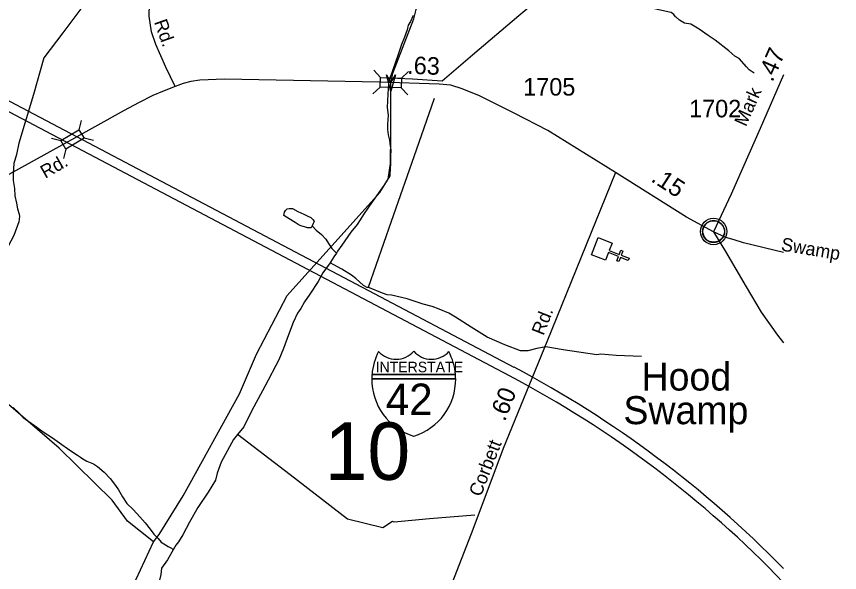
# Model space of a CAD drawing. Extents: x 2315291 to 2336543, y 597177 to 615230.
# Drawn here: x 2330575 to 2336451, y 602347 to 606314 of the extents above; entities that cross this region are included whole.
import ezdxf

# ---------------------------------------------------------------- set-up
doc = ezdxf.new("R2010")
doc.units = 0
for name, color, linetype in [('Exist Civil Demographics Community CELL', 7, 'Continuous'), ('Exist Civil Demographics Community Label', 7, 'Continuous'), ('Exist Cultural Church CELL', 7, 'Continuous'), ('Exist Hydrographic Creek Single Shore', 7, 'Continuous'), ('Exist Hydrographic Misc Water Feature', 7, 'Continuous'), ('Exist Road Primary US Attributed', 7, 'Continuous'), ('Exist Road Primary US Shield CELL', 7, 'Continuous'), ('Exist Road Primary US Shield Number Label', 7, 'Continuous'), ('Exist Road Secondary Mileage Hundredths English Label', 7, 'Continuous'), ('Exist Road Secondary Structure Standard Bridge Attributed CELL', 7, 'Continuous'), ('Exist Road Secondary Structure Standard Bridge CELL', 7, 'Continuous'), ('Exist Road Secondary Structure Standard Bridge Number Label', 7, 'Continuous'), ('Exist Road Secondary Type 51 Attributed', 7, 'Continuous'), ('Exist Road Secondary Type 51 Label', 7, 'Continuous'), ('Exist Road Secondary Type 51 Number Label', 7, 'Continuous')]:
    doc.layers.add(name, color=color, linetype=linetype)

msp = doc.modelspace()

# ---------------------------------------------------------------- linework, layer by layer
at = {"layer": 'Exist Civil Demographics Community CELL'}
msp.add_lwpolyline([(2335474.3, 604792.5), (2335475.3, 604798.1), (2335477.1, 604804.6), (2335480, 604811.8), (2335483, 604817.6), (2335486.3, 604823.3), (2335490.1, 604828.4), (2335494, 604832.8), (2335498.6, 604837.4), (2335504.1, 604842), (2335509.6, 604845.7), (2335514.4, 604848.5), (2335519.5, 604851), (2335525, 604853.3), (2335530.6, 604855.1), (2335534.9, 604856.2), (2335539.8, 604857), (2335543.9, 604857.7), (2335550.3, 604858), (2335554.7, 604857.9), (2335560.4, 604857.6), (2335565.3, 604856.9), (2335570.2, 604855.9), (2335575.2, 604854.5), (2335580.3, 604852.5), (2335587, 604849.6), (2335593.3, 604846.1), (2335598.3, 604842.6), (2335603.5, 604838.6), (2335606.8, 604835.4), (2335610.9, 604831), (2335614.8, 604826.3), (2335617.9, 604821.8), (2335621, 604816.7), (2335623.4, 604811.6), (2335625.5, 604806.6), (2335627, 604801.6), (2335628.3, 604797), (2335629.4, 604790.9), (2335630, 604786.2), (2335630.3, 604780.2), (2335630.1, 604774.4), (2335629.6, 604768.7), (2335628.6, 604763.3), (2335627, 604757.1), (2335625.1, 604751.3), (2335622.8, 604746.2), (2335619.6, 604740.2), (2335616.4, 604734.9), (2335612.9, 604730.2), (2335608.7, 604725.4), (2335603.4, 604720.5), (2335598.4, 604716.4), (2335593.4, 604712.9), (2335589, 604710.4), (2335582.2, 604707.2), (2335575.1, 604704.5), (2335569.1, 604703), (2335562.5, 604701.7), (2335558.1, 604701.2), (2335553.6, 604701), (2335548, 604701), (2335543.7, 604701.4), (2335538.1, 604702.1), (2335532.2, 604703.4), (2335527.6, 604704.7), (2335522.4, 604706.6), (2335517.8, 604708.6), (2335513.9, 604710.8), (2335507.1, 604714.9), (2335501.5, 604719.2), (2335496.6, 604723.7), (2335492.2, 604728.5), (2335489, 604732.5), (2335486, 604736.7), (2335481.9, 604743.8), (2335480.2, 604747.3), (2335478.5, 604751.3), (2335475.9, 604759.5), (2335474.3, 604766.6), (2335473.7, 604771.7), (2335473.3, 604778), (2335473.3, 604782.7), (2335473.8, 604789.2)], close=True, dxfattribs=at)
for centre, radius in [((2335552, 604780.1), 94.3), ((2335551.7, 604780.3), 76.7)]:
    msp.add_circle(centre, radius, dxfattribs=at)
at = {"layer": 'Exist Cultural Church CELL'}
msp.add_lwpolyline([(2334827.5, 604697.2), (2334806.8, 604644.1), (2334877.7, 604616.3), (2334889.4, 604646.1), (2334904.3, 604640.3), (2334892.6, 604610.5), (2334948.6, 604588.5), (2334942.7, 604573.6), (2334886.7, 604595.6), (2334875, 604565.8), (2334860.2, 604571.6), (2334871.8, 604601.4), (2334801, 604629.2), (2334779.8, 604575.6), (2334680.7, 604614.5), (2334728.4, 604736.1)], close=True, dxfattribs=at)
at = {"layer": 'Exist Hydrographic Creek Single Shore'}
for points in [[(2331553.5, 602566.1), (2331594.5, 602617), (2331766.4, 602893.1), (2332166.4, 603621.4), (2332288.4, 603905.2), (2332508.5, 604324.4), (2333168.2, 605058.9), (2333228.5, 605153.4), (2333244.6, 605266.1), (2333246.6, 605470.2), (2333248.1, 605841.5), (2333262.7, 605910.9), (2333411.5, 606298.5), (2333429.6, 606364.9), (2333467.8, 606503.8)], [(2331553.5, 602566.1), (2331368.4, 602712.9), (2331258.5, 602862.7), (2330879.5, 603234.6), (2330501.4, 603560.6)], [(2330983.5, 600534.7), (2330982.5, 600659.3), (2331029.4, 600936.9), (2331027.4, 601110.8), (2331050.5, 601243), (2331107.5, 601419.2), (2331430.5, 602298.7), (2331553.5, 602566.1)]]:
    msp.add_lwpolyline(points, dxfattribs=at)
at = {"layer": 'Exist Hydrographic Misc Water Feature'}
for points in [[(2331137.9, 606973.4), (2331096.5, 606687.2), (2331055.9, 606396.9), (2330906.2, 606197.6), (2330770, 606020.2), (2330696.6, 605757.5), (2330592.7, 605410.6), (2330575.4, 605328.4), (2330556.2, 605266), (2330553.1, 605195.9), (2330551.6, 605144.3), (2330560.3, 605086.2), (2330564.8, 605034.4), (2330575.4, 604982.5), (2330583.6, 604940.7), (2330595.9, 604904.8), (2330596.3, 604886.9), (2330592.7, 604848.9), (2330557.4, 604752.5), (2330493.2, 604629.9), (2330403.4, 604428.9), (2330321.2, 604254.3), (2330246.9, 604099.6)], [(2335284.9, 606308.6), (2335280.8, 606312.4), (2335268.5, 606328), (2335248.8, 606342), (2335224.2, 606347.7), (2334957.8, 606406.8), (2334551, 606496.4), (2334489.1, 606499.6), (2334418.9, 606509), (2334384.9, 606506.8), (2334161, 606318.2), (2333830.4, 606037.1), (2333614.3, 605852.6), (2333402.5, 605866.3), (2333240.7, 605874.8)], [(2333407.4, 606320.1), (2333388.1, 606278), (2333372.3, 606252), (2333364.8, 606219.9), (2333345.1, 606165.6), (2333323.5, 606115.4), (2333300.6, 606043.4), (2333281.3, 605989.1), (2333256.1, 605918.7), (2333242.5, 605880.6), (2333240.7, 605874.8)], [(2335842.4, 605909.6), (2335805.9, 605933.3), (2335785.8, 605955), (2335734.7, 606014.2), (2335703, 606031.9), (2335660.7, 606069.5), (2335563.5, 606144.2), (2335513.3, 606179.7), (2335448.7, 606222.7), (2335388, 606259), (2335343.7, 606266.1), (2335309.1, 606288.7), (2335284.9, 606308.6)], [(2333240.7, 605874.8), (2333230.4, 605836.6), (2333225.9, 605760.6), (2333222.7, 605664.6), (2333229.2, 605608.9), (2333224.1, 605542.7), (2333224.5, 605506.6), (2333228.8, 605468.6), (2333237.2, 605432.8), (2333241.5, 605407), (2333247.9, 605361.1), (2333244.4, 605317), (2333245, 605267), (2333243.2, 605221.1), (2333241.5, 605192.9), (2333239.7, 605177), (2333198.7, 605108.5), (2333109.9, 604983.6), (2333057, 604909.2), (2333007.8, 604830.6), (2332962.2, 604774.3), (2332897.4, 604683.4), (2332868.1, 604639.2), (2332859.7, 604625.4)], [(2333555.9, 605728), (2333427.5, 605360.8), (2333249.7, 604851), (2333086.7, 604379.6)], [(2332685.8, 604821.1), (2332678.4, 604807.2), (2332654, 604806.9), (2332630.5, 604812.4), (2332605.9, 604820.6), (2332586.2, 604830), (2332563.8, 604843.9), (2332521.4, 604869.4), (2332483, 604895), (2332489.2, 604918.9), (2332496.8, 604929.1), (2332508.7, 604941.5), (2332522.6, 604943.4), (2332544.8, 604943.7), (2332584.9, 604922.3), (2332605, 604912.4), (2332627.2, 604902.6), (2332651, 604892.9), (2332675.6, 604879), (2332693.2, 604863.4), (2332701.4, 604851.6), (2332693.6, 604837.4), (2332685.8, 604821.1)], [(2332685.8, 604821.1), (2332714.1, 604789.7), (2332752.7, 604758), (2332783, 604726.2), (2332803.3, 604694.4), (2332827.5, 604658.7), (2332859.7, 604625.4)], [(2332859.7, 604625.4), (2332840.2, 604599.2), (2332816.7, 604560.5), (2332814.8, 604556.8)], [(2332814.8, 604556.8), (2332763.5, 604486.2), (2332728.1, 604423.8), (2332669.2, 604333.3), (2332631.7, 604279), (2332606.3, 604230.9), (2332582.7, 604198.4), (2332551.7, 604130), (2332516.5, 604043.7), (2332481.4, 603945.5), (2332448.2, 603863.3), (2332427.1, 603823.1), (2332371.9, 603718.3), (2332330.7, 603642.2), (2332256.7, 603503.2), (2332197.6, 603386.8), (2332154.1, 603332.5)], [(2333086.7, 604379.6), (2333078.5, 604379.6), (2333052.3, 604395.3), (2332998.1, 604444.8), (2332965.9, 604468.4), (2332897.4, 604511.5), (2332841.1, 604543.1), (2332814.8, 604556.8)], [(2335036.5, 603887.2), (2334856.9, 603895.1), (2334747, 603903.9), (2334719.1, 603899.6), (2334476.8, 603934.9), (2334354.3, 603957.7), (2334290.6, 603945), (2334226.6, 603928.3), (2334172.5, 603927.5), (2334060.7, 603970.3), (2333934.2, 604025), (2333821.4, 604097.9), (2333708.6, 604168.4), (2333662.1, 604196.1), (2333591.7, 604225.3), (2333543.6, 604244.8), (2333477.5, 604262), (2333363.5, 604298.6), (2333253.2, 604325.8), (2333221, 604329), (2333189.2, 604339), (2333094.5, 604378), (2333086.7, 604379.6)], [(2330551, 603523), (2330593.5, 603485.4), (2330623.6, 603453.7), (2330720.4, 603384.8), (2330766.7, 603351.5), (2330833.2, 603308.2), (2330899.6, 603258.9), (2330940.2, 603231.3), (2330992.1, 603195.9), (2331010.6, 603184.2), (2331032.5, 603170.4), (2331048.7, 603158.6), (2331076.8, 603141), (2331125, 603121.5), (2331153.1, 603103.5), (2331201.9, 603062.2), (2331243.9, 603018.5), (2331282.5, 602967.3), (2331304.8, 602935.6), (2331333.5, 602887.8), (2331363.9, 602839.9), (2331408.4, 602796.7), (2331457, 602743.2), (2331493.2, 602701.6), (2331529.9, 602655.9), (2331556.4, 602620.3), (2331586.7, 602588.6), (2331608.9, 602562.9), (2331639, 602543), (2331659.3, 602531.4), (2331683.3, 602519.7), (2331695.2, 602507.8)], [(2332154.1, 603332.5), (2332124.8, 603296), (2332036.4, 603133.3), (2332007.3, 603054.9), (2331996, 603004.7), (2331942.9, 602920.2), (2331869.9, 602809.6), (2331811.3, 602706.9), (2331763.9, 602616.6), (2331730.9, 602566.1), (2331712.9, 602542), (2331695.2, 602507.8)], [(2333847.2, 602756.6), (2333523.9, 602729.4), (2333272.5, 602704.8), (2333258.5, 602710.5), (2333191.3, 602665.9), (2332938.2, 602727.1), (2332529.4, 603042.5), (2332154.1, 603332.5)], [(2331695.2, 602507.8), (2331654.2, 602437.3), (2331610.5, 602376.9), (2331605.4, 602332.7), (2331597.4, 602292.9)]]:
    msp.add_lwpolyline(points, dxfattribs=at)
at = {"layer": 'Exist Road Primary US Attributed'}
for p, q in [((2329596.5, 606199.9), (2334126.9, 603811.1)), ((2334094.5, 603749.6), (2329557.6, 606141.1))]:
    msp.add_line(p, q, dxfattribs=at)
for radius, start in [(7703.3, 44.27513), (7633.7, 43.73712)]:
    msp.add_arc((2330534.8, 596996.6), radius, start, 62.20482, dxfattribs=at)
at = {"layer": 'Exist Road Primary US Shield CELL'}
for p, q in [((2333113.7, 603760.7), (2333115.2, 603760.7)), ((2333709.2, 603760.7), (2333113.7, 603760.7)), ((2333115.2, 603760.7), (2333709.2, 603760.7)), ((2333115.2, 603760.7), (2333709.2, 603760.7)), ((2333112.2, 603729.2), (2333710.7, 603729.2)), ((2333710.7, 603729.2), (2333112.2, 603729.2)), ((2333112.2, 603729.2), (2333710.7, 603729.2))]:
    msp.add_line(p, q, dxfattribs=at)
for centre, radius, start, end in [((2333535.9, 603725.1), 424.1, 152.17537, 175.1644), ((2333284.9, 604035.9), 167.7, 222.29978, 318.85058), ((2333537.5, 604035.9), 167.7, 221.14942, 317.70026), ((2333286.5, 603725.1), 424.1, 4.81434, 27.82481), ((2333535.9, 603725.1), 424.1, 175.18566, 179.447), ((2333286.5, 603725.1), 424.1, 0.55256, 4.81266), ((2333535.9, 603725.1), 424.1, 179.46549, 252.79711), ((2333286.5, 603725.1), 424.1, 287.20289, 0.54051)]:
    msp.add_arc(centre, radius, start, end, dxfattribs=at)
at = {"layer": 'Exist Road Secondary Structure Standard Bridge Attributed CELL'}
msp.add_lwpolyline([(2333280.9, 605897.6), (2333246.8, 605780.5), (2333217.8, 605898.9), (2333248.1, 605841.5)], close=True, dxfattribs=at)
at = {"layer": 'Exist Road Secondary Structure Standard Bridge CELL'}
for p, q in [((2333125.6, 605930.2), (2333172.9, 605879.9)), ((2333323.9, 605874.9), (2333374.2, 605922.1)), ((2333120.4, 605762.1), (2333170.7, 605809.4)), ((2333321.7, 605805.9), (2333369, 605755.6)), ((2331038.4, 605573), (2331021.6, 605506.1)), ((2330892.5, 605427.5), (2330825.6, 605444.4)), ((2331124.7, 605428.6), (2331057.8, 605445.5)), ((2330927.9, 605368.3), (2330911, 605301.4))]:
    msp.add_line(p, q, dxfattribs=at)
for points in [[(2333172.9, 605879.9), (2333323.9, 605875.2), (2333321.7, 605804.7), (2333170.7, 605809.4)], [(2331057.8, 605445.5), (2330928, 605368), (2330891.8, 605428.6), (2331021.6, 605506.1)]]:
    msp.add_lwpolyline(points, close=True, dxfattribs=at)
at = {"layer": 'Exist Road Secondary Type 51 Attributed'}
for points in [[(2331707.5, 605814.9), (2331641.9, 605953.7), (2331570.7, 606114.4), (2331540.3, 606203.8), (2331523.2, 606316), (2331525.1, 606405.4), (2331528.9, 606525.2), (2331534.6, 606745.7), (2331542.2, 607085.2), (2331537.2, 607323.8), (2331509.9, 607762.1), (2331502, 607839.9), (2331470, 608157.6), (2331439.6, 608370.6)], [(2333167, 605844.4), (2332061, 605866.3), (2331884.3, 605860.6), (2331819.6, 605849.2), (2331764.5, 605835.9), (2331707.5, 605814.9)], [(2336050.3, 605897.6), (2335883.9, 605514), (2335678.2, 605047), (2335551.7, 604776.6)], [(2331707.5, 605814.9), (2331618.2, 605778.8), (2331549.8, 605750.3), (2331447.2, 605698.9), (2331344.6, 605643.8), (2330903.7, 605398.5), (2329533.5, 604641.7), (2328444.3, 604045.4), (2328357.6, 604007.1)], [(2334850.7, 605199.8), (2334368, 605501.2), (2334128.2, 605624.6), (2333879.6, 605748.4), (2333758, 605797.8), (2333676.3, 605824.4), (2333592.7, 605830.2), (2333167, 605844.4)], [(2334850.7, 605199.8), (2334362.3, 603993.3), (2334050.7, 603230.7), (2333834, 602652.7), (2333670.6, 602237.2)], [(2335551.7, 604776.6), (2335358.1, 604881.3), (2334850.7, 605199.8)], [(2336050.3, 604631.2), (2335765.3, 604700.1), (2335699.3, 604721.2), (2335638.7, 604737), (2335551.7, 604776.6)], [(2335551.7, 604776.6), (2335636.1, 604636.7), (2335783.7, 604386.1), (2335891.8, 604204.1), (2336007.8, 604040.5), (2336050.3, 603985.4)]]:
    msp.add_lwpolyline(points, dxfattribs=at)

# ---------------------------------------------------------------- texts
at = {"layer": 'Exist Civil Demographics Community Label'}
for s, p in [('Hood', (2335037.5, 603645.1)), ('Swamp', (2334908.1, 603405.1))]:
    msp.add_text(s, height=200, dxfattribs=at).set_placement(p)
at = {"layer": 'Exist Road Primary US Shield Number Label'}
for s, height, p in [('INTERSTATE', 75, (2333139.2, 603775.7)), ('42', 225, (2333211.2, 603469.7))]:
    msp.add_text(s, height=height, rotation=360, dxfattribs=at).set_placement(p)
at = {"layer": 'Exist Road Secondary Mileage Hundredths English Label'}
for s, rotation, p in [('.47', 66.0893, (2335971.4, 605841.1)), ('.63', 357.90479, (2333363, 605905.7)), ('.15', 327.10894, (2335098.1, 605142.4)), ('.60', 68.57913, (2334061.7, 603419.2))]:
    msp.add_text(s, height=125, rotation=rotation, dxfattribs=at).set_placement(p)
at = {"layer": 'Exist Road Secondary Structure Standard Bridge Number Label'}
msp.add_text('10', height=410.1, dxfattribs=at).set_placement((2332776, 603007.8))
at = {"layer": 'Exist Road Secondary Type 51 Label'}
for s, rotation, p in [('Rd.', 289.52425, (2331556.2, 606275.1)), ('Mark', 66.0893, (2335782.1, 605523.3)), ('Rd.', 29.63, (2330780.6, 605155.7)), ('Swamp', 350.53359, (2336028.8, 604644.6)), ('Rd.', 68.57913, (2334337.3, 604032.9)), ('Corbett', 68.85247, (2333890, 602881.9))]:
    msp.add_text(s, height=95, rotation=rotation, dxfattribs=at).set_placement(p)
at = {"layer": 'Exist Road Secondary Type 51 Number Label'}
for s, p in [('1705', (2334192.8, 605749.8)), ('1702', (2335376.9, 605594.5))]:
    msp.add_text(s, height=125, dxfattribs=at).set_placement(p)

doc.saveas('drawing.dxf')
